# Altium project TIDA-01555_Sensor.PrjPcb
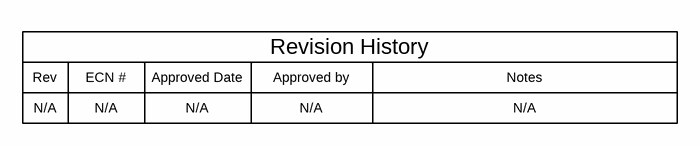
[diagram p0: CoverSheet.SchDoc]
CopyrightYear: 2017; PCB_Layout: Prasanna Rajagopal; PCB_Rev: E1; PRJ_Customer: Public Release; PRJ_Engineer: Prasanna Rajagopal; PRJ_Number: TIDA-01555; PRJ_Title: Enhanced Interface Reference Design to Connect Multiple ADCs to Processor for Input Expansion (48ch); SCH_Rev: E1; TechSupport: http://www.ti.com/support; TID: TIDA-01555
5 sheets, 139 parts. Net scope: global (net labels, ports and power ports of the same name join across sheets).
Board file: PCB.PcbDoc
Sheets:
  CoverSheet.SchDoc
  BlankSheet.SchDoc
  EVM_Hardware.SchDoc
  CT.SchDoc
  PT.SchDoc

## Sheet CoverSheet.SchDoc
size 431 x 279 mm; Date: Not shown in title block; ApprovedBy: Not shown in title block; CheckedBy: Not shown in title block; Author: Not shown in title block; CompanyName: Not shown in title block; Engineer: Not shown in title block; Organization: Not shown in title block; Address1: Not shown in title block; Address2: Not shown in title block; Address3: Not shown in title block; Address4: Not shown in title block; DocumentNumber: 1; Revision: Use project parameter SCH_Rev; SheetNumber: 1; SheetTotal: 3; PageSetup: Record=PageOptions¦CenterHorizontal=True¦CenterVertical=True¦PrintScale=1.00¦XCorrection=1.00¦YCorrection=1.00¦PrintKind=0¦BorderSize=5000000¦LeftOffset=0¦BottomOffset=0¦Orientation=2¦PaperLength=1000¦PaperWidth=1000¦Scale=100¦PaperSource=15¦PrintQuality=600¦MediaType=1¦DitherType=10¦PaperKind=Letter¦PrintScaleMode=1

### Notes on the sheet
- Rev
- N/A
- ECN #
- Approved Date
- Approved by
- Revision History
- Notes

## Sheet BlankSheet.SchDoc
size 431 x 279 mm; Date: Not shown in title block; ApprovedBy: Not shown in title block; CheckedBy: Not shown in title block; Author: Not shown in title block; CompanyName: Not shown in title block; Engineer: Not shown in title block; Organization: Not shown in title block; Address1: Not shown in title block; Address2: Not shown in title block; Address3: Not shown in title block; Address4: Not shown in title block; DocumentNumber: 1; Revision: Use project parameter SCH_Rev; SheetNumber: 2; SheetTotal: 3; PageSetup: Record=PageOptions¦CenterHorizontal=True¦CenterVertical=True¦PrintScale=1.00¦XCorrection=1.00¦YCorrection=1.00¦PrintKind=0¦BorderSize=5000000¦LeftOffset=0¦BottomOffset=0¦Orientation=2¦PaperLength=1000¦PaperWidth=1000¦Scale=100¦PaperSource=15¦PrintQuality=600¦MediaType=1¦DitherType=10¦PaperKind=Letter¦PrintScaleMode=1

## Sheet EVM_Hardware.SchDoc
size 431 x 279 mm; Date: Not shown in title block; ApprovedBy: Not shown in title block; CheckedBy: Not shown in title block; Author: Not shown in title block; CompanyName: Not shown in title block; Engineer: Not shown in title block; Organization: Not shown in title block; Address1: Not shown in title block; Address2: Not shown in title block; Address3: Not shown in title block; Address4: Not shown in title block; DocumentNumber: 1; Revision: Use project parameter SCH_Rev; SheetNumber: 3; SheetTotal: 3; PageSetup: Record=PageOptions¦CenterHorizontal=True¦CenterVertical=True¦PrintScale=1.00¦XCorrection=1.00¦YCorrection=1.00¦PrintKind=0¦BorderSize=5000000¦LeftOffset=0¦BottomOffset=0¦Orientation=2¦PaperLength=1000¦PaperWidth=1000¦Scale=100¦PaperSource=15¦PrintQuality=600¦MediaType=1¦DitherType=10¦PaperKind=Letter¦PrintScaleMode=1
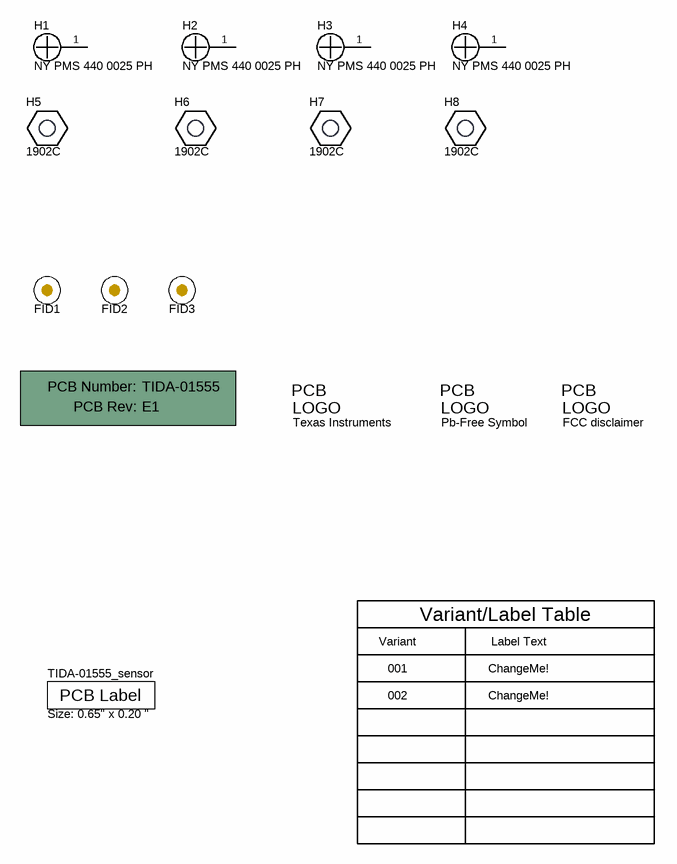
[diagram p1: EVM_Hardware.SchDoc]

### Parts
!PCB1  Printed Circuit Board  (value not drawn)  (mechanical)
FID1  Fiducial  [Fiducial10-20]  (value not drawn)
FID2  Fiducial  [Fiducial10-20]  (value not drawn)
FID3  Fiducial  [Fiducial10-20]  (value not drawn)
H1  NY PMS 440 0025 PH  [NY PMS 440 0025 PH]
H2  NY PMS 440 0025 PH  [NY PMS 440 0025 PH]
H3  NY PMS 440 0025 PH  [NY PMS 440 0025 PH]
H4  NY PMS 440 0025 PH  [NY PMS 440 0025 PH]
H5  1902C  [Keystone_1902C]
H6  1902C  [Keystone_1902C]
H7  1902C  [Keystone_1902C]
H8  1902C  [Keystone_1902C]
Logo1  Texas Instruments  [TI_Stacked_Overlay_Small]  (no BOM)
Logo2  Pb-Free Symbol  [Pb-Free_Overlay_Small]  (no BOM)
Logo3  FCC disclaimer  [FCC_disclaimer]  (no BOM)
TIDA-01555_sensor  Size: 0.65" x 0.20 "  [Label_650x200]

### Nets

Not connected (* = marked no-connect by the designer): H1 1; H2 1; H3 1; H4 1

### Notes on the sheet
- Variant
- Variant/Label Table
- Label Text
- 001
- 002
- ChangeMe!

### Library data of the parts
!PCB1 = PCB: Manufacturer: Any; PartNumber: TIDA-01555; SymbolCreator: a0412235
FID1-FID3 = Fiducial: Fiducial mark.  There is nothing to buy or mount.; SymbolCreator: codlsc
H1-H4 = NY PMS 440 0025 PH: Machine Screw, Round, #4-40 x 1/4, Nylon, Philips panhead; Manufacturer: B&F Fastener Supply; CompType: Hardware; SymbolCreator: codlsc; U/M: EA
H5-H8 = 1902C: Standoff, Hex, 0.5"L #4-40 Nylon; Manufacturer: Keystone; CompType: Hardware
Logo1 = TI_Logo: Texas Instrument Corporate Signature; SymbolCreator: codlsc
Logo2 = Pb-Free: SymbolCreator: a0412235
Logo3 = FCC_disclaimer: SymbolCreator: codlsc
TIDA-01555_sensor = THT-14-423-10: Thermal Transfer Printable Labels, 0.650" W x 0.200" H - 10,000 per roll; Manufacturer: Brady; SymbolCreator: a0412235; CompType: Label

## Sheet CT.SchDoc
size 431 x 279 mm; Date: Not shown in title block; ApprovedBy: Not shown in title block; CheckedBy: Not shown in title block; Author: Not shown in title block; CompanyName: Not shown in title block; Engineer: Not shown in title block; Organization: Not shown in title block; Address1: Not shown in title block; Address2: Not shown in title block; Address3: Not shown in title block; Address4: Not shown in title block; DocumentNumber: 1; Revision: Use project parameter SCH_Rev; SheetNumber: 2; SheetTotal: 3; PageSetup: Record=PageOptions¦CenterHorizontal=True¦CenterVertical=True¦PrintScale=1.00¦XCorrection=1.00¦YCorrection=1.00¦PrintKind=0¦BorderSize=5000000¦LeftOffset=0¦BottomOffset=0¦Orientation=2¦PaperLength=1000¦PaperWidth=1000¦Scale=100¦PaperSource=15¦PrintQuality=600¦MediaType=1¦DitherType=10¦PaperKind=Letter¦PrintScaleMode=1
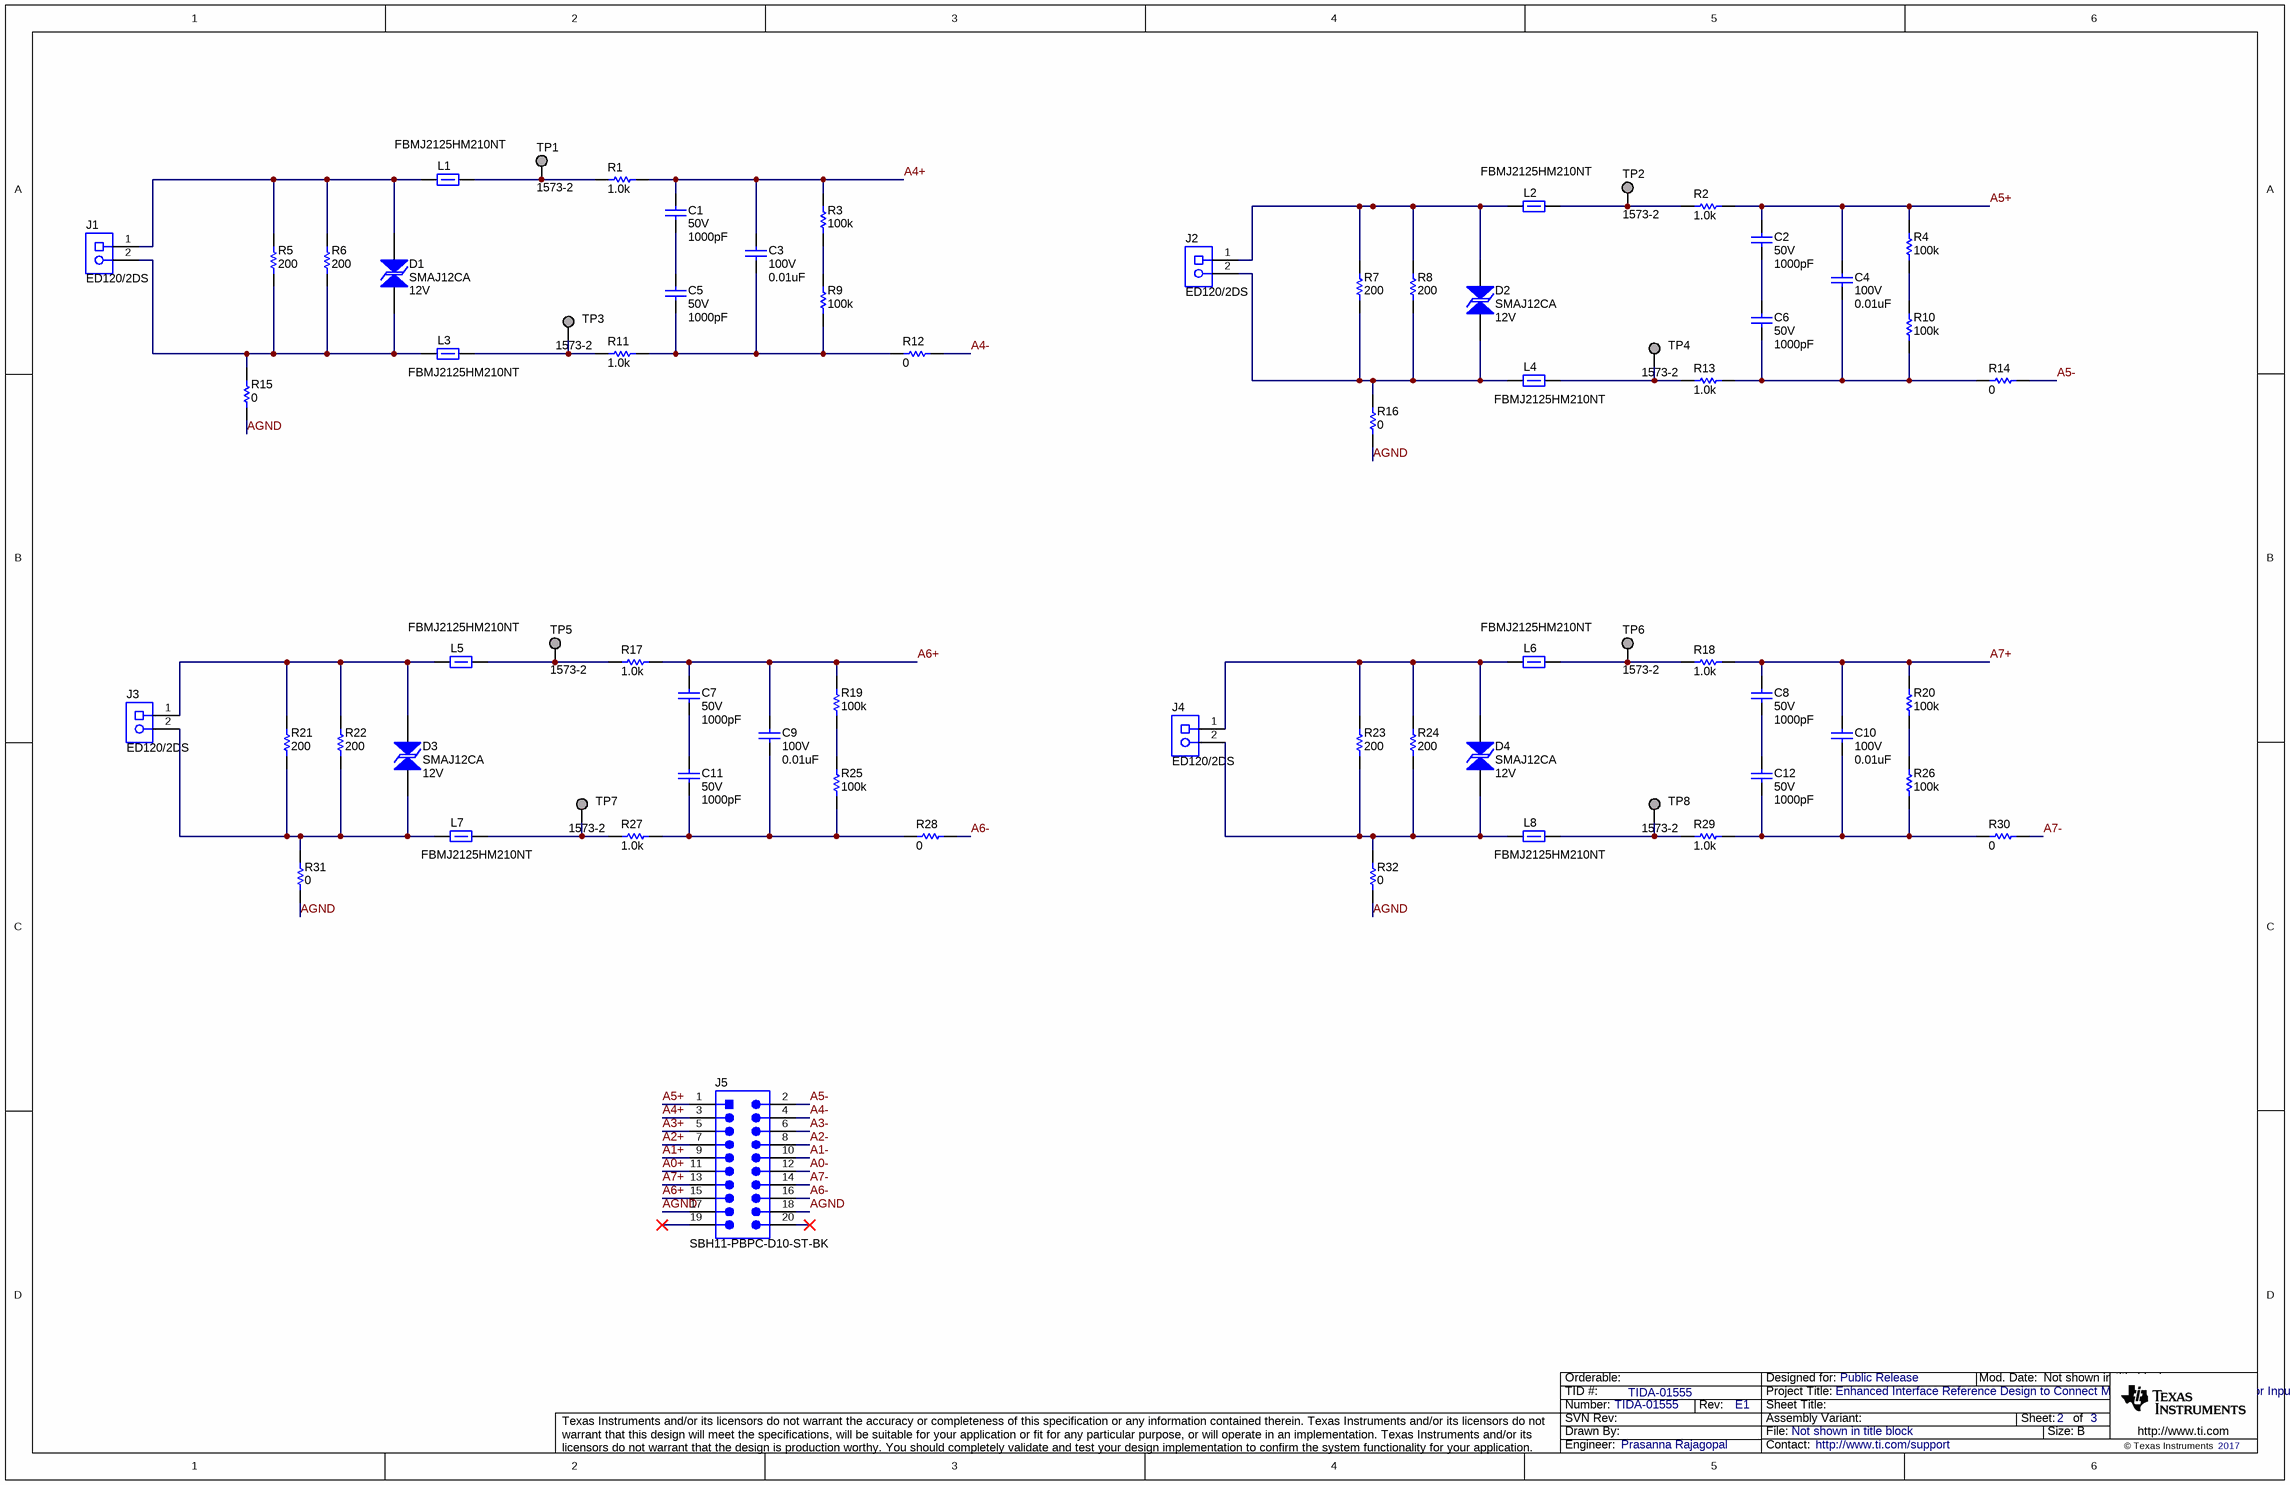
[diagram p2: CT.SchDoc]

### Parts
C1  VDC_V: 50V  ValueDisplayed: 1000pF  [0603]  (hidden comment: C0603X102K5RACTU)
C2  VDC_V: 50V  ValueDisplayed: 1000pF  [0603]  (hidden comment: C0603X102K5RACTU)
C3  VDC_V: 100V  ValueDisplayed: 0.01uF  [0603]  (hidden comment: 06031C103JAT2A)
C4  VDC_V: 100V  ValueDisplayed: 0.01uF  [0603]  (hidden comment: 06031C103JAT2A)
C5  VDC_V: 50V  ValueDisplayed: 1000pF  [0603]  (hidden comment: C0603X102K5RACTU)
C6  VDC_V: 50V  ValueDisplayed: 1000pF  [0603]  (hidden comment: C0603X102K5RACTU)
C7  VDC_V: 50V  ValueDisplayed: 1000pF  [0603]  (hidden comment: C0603X102K5RACTU)
C8  VDC_V: 50V  ValueDisplayed: 1000pF  [0603]  (hidden comment: C0603X102K5RACTU)
C9  VDC_V: 100V  ValueDisplayed: 0.01uF  [0603]  (hidden comment: 06031C103JAT2A)
C10  VDC_V: 100V  ValueDisplayed: 0.01uF  [0603]  (hidden comment: 06031C103JAT2A)
C11  VDC_V: 50V  ValueDisplayed: 1000pF  [0603]  (hidden comment: C0603X102K5RACTU)
C12  VDC_V: 50V  ValueDisplayed: 1000pF  [0603]  (hidden comment: C0603X102K5RACTU)
D1  SMAJ12CA  value 12V  [SMA]
D2  SMAJ12CA  value 12V  [SMA]
D3  SMAJ12CA  value 12V  [SMA]
D4  SMAJ12CA  value 12V  [SMA]
J1  ED120/2DS  [On-Shore_ED120_2DS]
J2  ED120/2DS  [On-Shore_ED120_2DS]
J3  ED120/2DS  [On-Shore_ED120_2DS]
J4  ED120/2DS  [On-Shore_ED120_2DS]
J5  SBH11-PBPC-D10-ST-BK  [Sullins_SBH11-xxxC-D10-ST]
L1  FBMJ2125HM210NT  [0805_HV]
L2  FBMJ2125HM210NT  [0805_HV]
L3  FBMJ2125HM210NT  [0805_HV]
L4  FBMJ2125HM210NT  [0805_HV]
L5  FBMJ2125HM210NT  [0805_HV]
L6  FBMJ2125HM210NT  [0805_HV]
L7  FBMJ2125HM210NT  [0805_HV]
L8  FBMJ2125HM210NT  [0805_HV]
R1  ValueDisplayed: 1.0k  [0603]  (hidden comment: CRCW06031K00JNEA)
R2  ValueDisplayed: 1.0k  [0603]  (hidden comment: CRCW06031K00JNEA)
R3  ValueDisplayed: 100k  [0603]  (hidden comment: RC0603FR-07100KL)
R4  ValueDisplayed: 100k  [0603]  (hidden comment: RC0603FR-07100KL)
R5  ValueDisplayed: 200  [0603]  (hidden comment: CRCW0603200RFKEA)
R6  ValueDisplayed: 200  [0603]  (hidden comment: CRCW0603200RFKEA)
R7  ValueDisplayed: 200  [0603]  (hidden comment: CRCW0603200RFKEA)
R8  ValueDisplayed: 200  [0603]  (hidden comment: CRCW0603200RFKEA)
R9  ValueDisplayed: 100k  [0603]  (hidden comment: RC0603FR-07100KL)
R10  ValueDisplayed: 100k  [0603]  (hidden comment: RC0603FR-07100KL)
R11  ValueDisplayed: 1.0k  [0603]  (hidden comment: CRCW06031K00JNEA)
R12  ValueDisplayed: 0  [0603]  (hidden comment: CRCW06030000Z0EA)
R13  ValueDisplayed: 1.0k  [0603]  (hidden comment: CRCW06031K00JNEA)
R14  ValueDisplayed: 0  [0603]  (hidden comment: CRCW06030000Z0EA)
R15  ValueDisplayed: 0  [0603]  (hidden comment: CRCW06030000Z0EA)
R16  ValueDisplayed: 0  [0603]  (hidden comment: CRCW06030000Z0EA)
R17  ValueDisplayed: 1.0k  [0603]  (hidden comment: CRCW06031K00JNEA)
R18  ValueDisplayed: 1.0k  [0603]  (hidden comment: CRCW06031K00JNEA)
R19  ValueDisplayed: 100k  [0603]  (hidden comment: RC0603FR-07100KL)
R20  ValueDisplayed: 100k  [0603]  (hidden comment: RC0603FR-07100KL)
R21  ValueDisplayed: 200  [0603]  (hidden comment: CRCW0603200RFKEA)
R22  ValueDisplayed: 200  [0603]  (hidden comment: CRCW0603200RFKEA)
R23  ValueDisplayed: 200  [0603]  (hidden comment: CRCW0603200RFKEA)
R24  ValueDisplayed: 200  [0603]  (hidden comment: CRCW0603200RFKEA)
R25  ValueDisplayed: 100k  [0603]  (hidden comment: RC0603FR-07100KL)
R26  ValueDisplayed: 100k  [0603]  (hidden comment: RC0603FR-07100KL)
R27  ValueDisplayed: 1.0k  [0603]  (hidden comment: CRCW06031K00JNEA)
R28  ValueDisplayed: 0  [0603]  (hidden comment: CRCW06030000Z0EA)
R29  ValueDisplayed: 1.0k  [0603]  (hidden comment: CRCW06031K00JNEA)
R30  ValueDisplayed: 0  [0603]  (hidden comment: CRCW06030000Z0EA)
R31  ValueDisplayed: 0  [0603]  (hidden comment: CRCW06030000Z0EA)
R32  ValueDisplayed: 0  [0603]  (hidden comment: CRCW06030000Z0EA)
TP1  1573-2  [Keystone1573-2]
TP2  1573-2  [Keystone1573-2]
TP3  1573-2  [Keystone1573-2]
TP4  1573-2  [Keystone1573-2]
TP5  1573-2  [Keystone1573-2]
TP6  1573-2  [Keystone1573-2]
TP7  1573-2  [Keystone1573-2]
TP8  1573-2  [Keystone1573-2]

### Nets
A0+: J5.11
A0-: J5.12
A1+: J5.9
A1-: J5.10
A2+: J5.7
A2-: J5.8
A3+: J5.5
A3-: J5.6
A4+: C1.1 C3.1 J5.3 R1.1 R3.2
A4-: J5.4 R12.2
A5+: C2.1 C4.1 J5.1 R2.1 R4.2
A5-: J5.2 R14.2
A6+: C7.1 C9.1 J5.15 R17.1 R19.2
A6-: J5.16 R28.2
A7+: C8.1 C10.1 J5.13 R18.1 R20.2
A7-: J5.14 R30.2
AGND: J5.17 J5.18 R15.1 R16.1 R31.1 R32.1
NetC1_2: C1.2 C5.1
NetC2_2: C2.2 C6.1
NetC3_2: C3.2 C5.2 R9.1 R11.1 R12.1
NetC4_2: C4.2 C6.2 R10.1 R13.1 R14.1
NetC7_2: C7.2 C11.1
NetC8_2: C8.2 C12.1
NetC9_2: C9.2 C11.2 R25.1 R27.1 R28.1
NetC10_2: C10.2 C12.2 R26.1 R29.1 R30.1
NetD1_1: D1.1 J1.2 L3.1 R5.1 R6.1 R15.2
NetD1_2: D1.2 J1.1 L1.1 R5.2 R6.2
NetD2_1: D2.1 J2.2 L4.1 R7.1 R8.1 R16.2
NetD2_2: D2.2 J2.1 L2.1 R7.2 R8.2
NetD3_1: D3.1 J3.2 L7.1 R21.1 R22.1 R31.2
NetD3_2: D3.2 J3.1 L5.1 R21.2 R22.2
NetD4_1: D4.1 J4.2 L8.1 R23.1 R24.1 R32.2
NetD4_2: D4.2 J4.1 L6.1 R23.2 R24.2
NetL1_2: L1.2 R1.2 TP1.1
NetL2_2: L2.2 R2.2 TP2.1
NetL3_2: L3.2 R11.2 TP3.1
NetL4_2: L4.2 R13.2 TP4.1
NetL5_2: L5.2 R17.2 TP5.1
NetL6_2: L6.2 R18.2 TP6.1
NetL7_2: L7.2 R27.2 TP7.1
NetL8_2: L8.2 R29.2 TP8.1
NetR3_1: R3.1 R9.2
NetR4_1: R4.1 R10.2
NetR19_1: R19.1 R25.2
NetR20_1: R20.1 R26.2

Not connected (* = marked no-connect by the designer): J5 19* 20*

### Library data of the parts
C1 C2 C5-C8 C11 C12 = CMP-0006976-5: CAP, CERM, 1000 pF, 50 V, +/- 10%, X7R, 0603; Manufacturer: Kemet; TaMin_C: -55°C; Polarized: N; SizeAreaWB_mm2: 4.68; Value1: Unknown; U/M: EA; Value: 1000pF; TaMax_C: 125°C; SizeZ_mm: 1; SizeX_mm: 1.6; SizeY_mm: 0.8; SizeArea_mm2: 1.28; Cap_F: 1nF; AEC Category: Q200
C3 C4 C9 C10 = CMP-0006726-4: CAP, CERM, 0.01 uF, 100 V, +/- 5%, X7R, 0603; Manufacturer: AVX; TaMin_C: -55°C; ESR_ohm: 0.098; Polarized: N; SizeAreaWB_mm2: 4.68; Value1: 0.098 ohm; U/M: EA; Value: 0.01uF; TaMax_C: 125°C; SizeZ_mm: 1; SizeX_mm: 1.6; SizeY_mm: 0.8; SizeArea_mm2: 1.28; Cap_F: 10nF; AEC Category: Q200
D1-D4 = CMP-0005430-2: Diode, TVS, Bi, 12 V, SMA; Manufacturer: Littelfuse; Power_W: 3.3W; SizeAreaWB_mm2: 37.3428; RJA_CperW: 120; U/M: EA; SizeZ_mm: 2.87; SizeX_mm: 5.59; SizeY_mm: 2.92; SizeArea_mm2: 16.3228; AEC Category: Q101
J1-J4 = CMP-0074910-1: Terminal Block, 5.08 mm, 2x1, Brass, TH; Manufacturer: On-Shore Technology; Cert_VDE: Y; CNHeader: False; Current_A: 15A; Green_Lifecycle: Not Set; Shrouded: N; Gender: Female; Green_REACh: Incomplete; Voltage_V: 300V; Row_Count: 1; Pitch_mm: 5.08; CT: True
J5 = SBH11-PBPC-D10-ST-BK: Header (Shrouded), 2.54mm, 10x2, Gold, Black, TH; Manufacturer: Sullins Connector Solutions; SymbolCreator: a0412235; Pitch_mm: 2.54; Gender: Male; Shrouded: Y; Row_Count: 2; Current_A: 3; Voltage_V: 1000; Green_Lifecycle: Not Set; Green_REACh: Incomplete
L1-L8 = CMP-0003375-1: Ferrite Bead, 21 ohm @ 100 MHz, 6 A, 0805; Manufacturer: Taiyo Yuden; ZTyp@100MHz_Ohm: 21; SizeAreaWB_mm2: 6.75; DCR_ohm: 4m; Value1: 0.004 ohm; Value: 21 ohm; Imax_A: 6A; SizeZ_mm: 1.45; SizeX_mm: 2; SizeY_mm: 1.25; SizeArea_mm2: 2.5
R1 R2 R11 R13 R17 R18 R27 R29 = CRCW06031K00JNEA: RES, 1.0 k, 5%, 0.1 W, 0603; Manufacturer: Vishay-Dale; CompType: Resistor; Value: 1.0k; Res_ohm: 1000; Value_Code: 1k00; Tolerance_%: 5; Power_W: 0.1; Value2: 0.1W; VDC_V: 75; TempCo: 200 ppm/C; SizeArea_mm2: 1.28; SizeX_mm: 1.6; SizeY_mm: 0.8; SizeZ_mm: 1; EIA_Code: E24; U/M: EA; AEC Category: Q200; Green_Lifecycle: Active; Green_REACh: Passed
R3 R4 R9 R10 R19 R20 R25 R26 = CMP-0022735-3: RES, 100 k, 1%, 0.1 W, 0603; Manufacturer: Yageo America; Power_W: 100mW; TempCo: 200 ppm/C; U/M: EA; Value: 100k; EIA_Code: E96; SizeX_mm: 1.6; SizeY_mm: 0.8; SizeZ_mm: 1; Value2: 0.1W; SizeArea_mm2: 1.28; VDC_V: 150V; AEC Category: Q200
R5-R8 R21-R24 = CRCW0603200RFKEA: RES, 200, 1%, 0.1 W, 0603; Manufacturer: Vishay-Dale; CompType: Resistor; Value: 200; Value_Code: 200R; Tolerance_%: 1; Power_W: 0.1; Value2: 0.1W; VDC_V: 75; TempCo: 100 ppm/C; SizeArea_mm2: 1.28; SizeX_mm: 1.6; SizeY_mm: 0.8; EIA_Code: E96; U/M: EA; AEC Category: Q200; Green_Lifecycle: Active; Green_REACh: Passed
R12 R14 R28 R30 = CMP-0025697-3: RES, 0, 5%, 0.1 W, 0603; Manufacturer: Vishay-Dale; Power_W: 100mW; TempCo: 200 ppm/C; Value_Code: 0000; U/M: EA; Value: 0; EIA_Code: E24; SizeX_mm: 1.6; SizeY_mm: 0.8; SizeZ_mm: 1; Value2: 0.1W; SizeArea_mm2: 1.28; VDC_V: 75V; AEC Category: Q200
R15 R16 R31 R32 = CMP-0025697-3: RES, 0, 5%, 0.1 W, 0603; Manufacturer: Vishay-Dale; Power_W: 100mW; TempCo: 200 ppm/C; Value_Code: 0000; U/M: EA; Value: 0; EIA_Code: E24; SizeX_mm: 1.6; SizeY_mm: 0.8; SizeZ_mm: 1; Value2: 0.1W; SizeArea_mm2: 1.28; CompType: Resistor; VDC_V: 75V; AEC Category: Q200
TP1-TP8 = CMP-0055119-1: Terminal, Turret, TH, Double; Manufacturer: Keystone; CT: FALSE; Green_REACh: Passed; CompType: Turret Terminal; Green_Lifecycle: Active

## Sheet PT.SchDoc
size 431 x 279 mm; Date: Not shown in title block; ApprovedBy: Not shown in title block; CheckedBy: Not shown in title block; Author: Not shown in title block; CompanyName: Not shown in title block; Engineer: Not shown in title block; Organization: Not shown in title block; Address1: Not shown in title block; Address2: Not shown in title block; Address3: Not shown in title block; Address4: Not shown in title block; DocumentNumber: 1; Revision: Use project parameter SCH_Rev; SheetNumber: 2; SheetTotal: 3; PageSetup: Record=PageOptions¦CenterHorizontal=True¦CenterVertical=True¦PrintScale=1.00¦XCorrection=1.00¦YCorrection=1.00¦PrintKind=0¦BorderSize=5000000¦LeftOffset=0¦BottomOffset=0¦Orientation=2¦PaperLength=1000¦PaperWidth=1000¦Scale=100¦PaperSource=15¦PrintQuality=600¦MediaType=1¦DitherType=10¦PaperKind=Letter¦PrintScaleMode=1
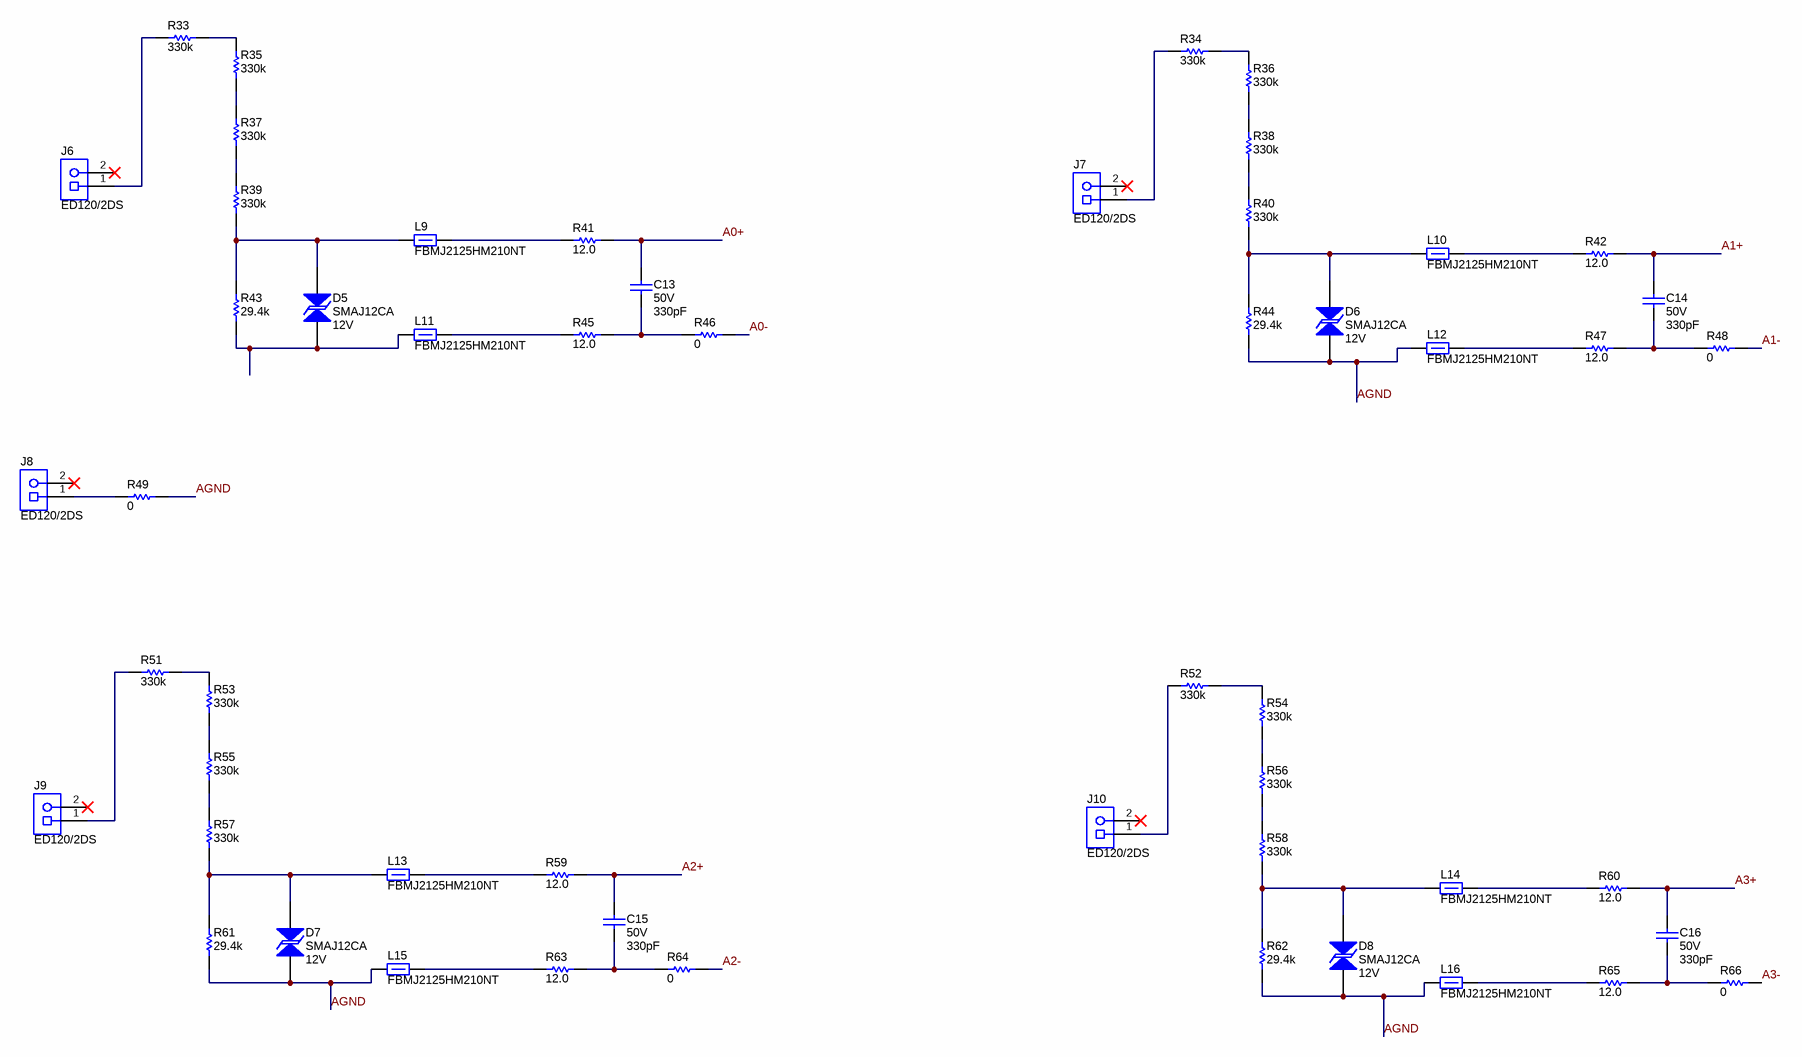
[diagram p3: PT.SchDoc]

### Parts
C13  VDC_V: 50V  ValueDisplayed: 330pF  [0805_HV]  (hidden comment: 08055A331KAT2A)
C14  VDC_V: 50V  ValueDisplayed: 330pF  [0805_HV]  (hidden comment: 08055A331KAT2A)
C15  VDC_V: 50V  ValueDisplayed: 330pF  [0805_HV]  (hidden comment: 08055A331KAT2A)
C16  VDC_V: 50V  ValueDisplayed: 330pF  [0805_HV]  (hidden comment: 08055A331KAT2A)
D5  SMAJ12CA  value 12V  [SMA]
D6  SMAJ12CA  value 12V  [SMA]
D7  SMAJ12CA  value 12V  [SMA]
D8  SMAJ12CA  value 12V  [SMA]
J6  ED120/2DS  [On-Shore_ED120_2DS]
J7  ED120/2DS  [On-Shore_ED120_2DS]
J8  ED120/2DS  [On-Shore_ED120_2DS]
J9  ED120/2DS  [On-Shore_ED120_2DS]
J10  ED120/2DS  [On-Shore_ED120_2DS]
L9  FBMJ2125HM210NT  [0805_HV]
L10  FBMJ2125HM210NT  [0805_HV]
L11  FBMJ2125HM210NT  [0805_HV]
L12  FBMJ2125HM210NT  [0805_HV]
L13  FBMJ2125HM210NT  [0805_HV]
L14  FBMJ2125HM210NT  [0805_HV]
L15  FBMJ2125HM210NT  [0805_HV]
L16  FBMJ2125HM210NT  [0805_HV]
R33  ValueDisplayed: 330k  [1206]  (hidden comment: RC1206FR-07330KL)
R34  ValueDisplayed: 330k  [1206]  (hidden comment: RC1206FR-07330KL)
R35  ValueDisplayed: 330k  [1206]  (hidden comment: RC1206FR-07330KL)
R36  ValueDisplayed: 330k  [1206]  (hidden comment: RC1206FR-07330KL)
R37  ValueDisplayed: 330k  [1206]  (hidden comment: RC1206FR-07330KL)
R38  ValueDisplayed: 330k  [1206]  (hidden comment: RC1206FR-07330KL)
R39  ValueDisplayed: 330k  [1206]  (hidden comment: RC1206FR-07330KL)
R40  ValueDisplayed: 330k  [1206]  (hidden comment: RC1206FR-07330KL)
R41  ValueDisplayed: 12.0  [0603]  (hidden comment: RC0603FR-0712RL)
R42  ValueDisplayed: 12.0  [0603]  (hidden comment: RC0603FR-0712RL)
R43  ValueDisplayed: 29.4k  [1206]  (hidden comment: CRCW120629K4FKEA)
R44  ValueDisplayed: 29.4k  [1206]  (hidden comment: CRCW120629K4FKEA)
R45  ValueDisplayed: 12.0  [0603]  (hidden comment: RC0603FR-0712RL)
R46  ValueDisplayed: 0  [0603]  (hidden comment: CRCW06030000Z0EA)
R47  ValueDisplayed: 12.0  [0603]  (hidden comment: RC0603FR-0712RL)
R48  ValueDisplayed: 0  [0603]  (hidden comment: CRCW06030000Z0EA)
R49  ValueDisplayed: 0  [0603]  (hidden comment: CRCW06030000Z0EA)
R51  ValueDisplayed: 330k  [1206]  (hidden comment: RC1206FR-07330KL)
R52  ValueDisplayed: 330k  [1206]  (hidden comment: RC1206FR-07330KL)
R53  ValueDisplayed: 330k  [1206]  (hidden comment: RC1206FR-07330KL)
R54  ValueDisplayed: 330k  [1206]  (hidden comment: RC1206FR-07330KL)
R55  ValueDisplayed: 330k  [1206]  (hidden comment: RC1206FR-07330KL)
R56  ValueDisplayed: 330k  [1206]  (hidden comment: RC1206FR-07330KL)
R57  ValueDisplayed: 330k  [1206]  (hidden comment: RC1206FR-07330KL)
R58  ValueDisplayed: 330k  [1206]  (hidden comment: RC1206FR-07330KL)
R59  ValueDisplayed: 12.0  [0603]  (hidden comment: RC0603FR-0712RL)
R60  ValueDisplayed: 12.0  [0603]  (hidden comment: RC0603FR-0712RL)
R61  ValueDisplayed: 29.4k  [1206]  (hidden comment: CRCW120629K4FKEA)
R62  ValueDisplayed: 29.4k  [1206]  (hidden comment: CRCW120629K4FKEA)
R63  ValueDisplayed: 12.0  [0603]  (hidden comment: RC0603FR-0712RL)
R64  ValueDisplayed: 0  [0603]  (hidden comment: CRCW06030000Z0EA)
R65  ValueDisplayed: 12.0  [0603]  (hidden comment: RC0603FR-0712RL)
R66  ValueDisplayed: 0  [0603]  (hidden comment: CRCW06030000Z0EA)

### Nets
A0+: C13.1 R41.2
A0-: R46.2
A1+: C14.1 R42.2
A1-: R48.2
A2+: C15.1 R59.2
A2-: R64.2
A3+: C16.1 R60.2
A3-: R66.2
AGND: D6.1 D7.1 D8.1 L12.1 L15.1 L16.1 R44.2 R49.1 R61.2 R62.2
NetC13_2: C13.2 R45.2 R46.1
NetC14_2: C14.2 R47.2 R48.1
NetC15_2: C15.2 R63.2 R64.1
NetC16_2: C16.2 R65.2 R66.1
NetD5_1: D5.1 L11.1 R43.2
NetD5_2: D5.2 L9.1 R39.1 R43.1
NetD6_2: D6.2 L10.1 R40.1 R44.1
NetD7_2: D7.2 L13.1 R57.1 R61.1
NetD8_2: D8.2 L14.1 R58.1 R62.1
NetJ6_1: J6.1 R33.2
NetJ7_1: J7.1 R34.2
NetJ8_1: J8.1 R49.2
NetJ9_1: J9.1 R51.2
NetJ10_1: J10.1 R52.2
NetL9_2: L9.2 R41.1
NetL10_2: L10.2 R42.1
NetL11_2: L11.2 R45.1
NetL12_2: L12.2 R47.1
NetL13_2: L13.2 R59.1
NetL14_2: L14.2 R60.1
NetL15_2: L15.2 R63.1
NetL16_2: L16.2 R65.1
NetR33_1: R33.1 R35.2
NetR34_1: R34.1 R36.2
NetR35_1: R35.1 R37.2
NetR36_1: R36.1 R38.2
NetR37_1: R37.1 R39.2
NetR38_1: R38.1 R40.2
NetR51_1: R51.1 R53.2
NetR52_1: R52.1 R54.2
NetR53_1: R53.1 R55.2
NetR54_1: R54.1 R56.2
NetR55_1: R55.1 R57.2
NetR56_1: R56.1 R58.2

Not connected (* = marked no-connect by the designer): J6 2*; J7 2*; J8 2*; J9 2*; J10 2*

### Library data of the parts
C13-C16 = CMP-0007609-2: CAP, CERM, 330 pF, 50 V, +/- 10%, C0G/NP0, 0805; Manufacturer: AVX; TaMin_C: -55°C; ESR_ohm: 1.89d; Polarized: N; SizeAreaWB_mm2: 6.75; Value1: 0.189 ohm; U/M: EA; Value: 330pF; TaMax_C: 125°C; SizeZ_mm: 1.45; SizeX_mm: 2; SizeY_mm: 1.25; Cap_Case: 0805; SizeArea_mm2: 2.5; AEC Category: Q200
D5-D8 = CMP-0005430-2: as D1 on sheet CT
J6-J10 = CMP-0074910-1: as J1 on sheet CT
L9-L16 = CMP-0003375-1: as L1 on sheet CT
R33-R40 R51-R58 = CMP-0018205-2: RES, 330 k, 1%, 0.25 W, 1206; Manufacturer: Yageo America; Power_W: 250mW; TempCo: 100 ppm/C; U/M: EA; Value: 330k; SizeX_mm: 3.2; SizeY_mm: 1.6; SizeZ_mm: 1.35; Value2: 0.25W; SizeArea_mm2: 5.12; VDC_V: 200V; AEC Category: Q200
R41 R42 R45 R47 R59 R60 R63 R65 = CMP-0022783-2: RES, 12.0, 1%, 0.1 W, 0603; Manufacturer: Yageo America; Power_W: 100mW; TempCo: 200 ppm/C; Value_Code: 12R0; U/M: EA; Value: 12.0; Res_ohm: 12; SizeX_mm: 1.6; SizeY_mm: 0.8; SizeZ_mm: 1; Value2: 0.1W; SizeArea_mm2: 1.28; VDC_V: 150V; AEC Category: Q200
R43 R44 R61 R62 = CMP-0016842-2: RES, 29.4 k, 1%, 0.25 W, 1206; Manufacturer: Vishay-Dale; Power_W: 250mW; TempCo: 100 ppm/C; Value_Code: 29k4; U/M: EA; Value: 29.4k; SizeX_mm: 3.2; SizeY_mm: 1.6; SizeZ_mm: 1.35; Value2: 0.25W; SizeArea_mm2: 5.12; VDC_V: 200V; AEC Category: Q200; EIA_Code: E96
R46 R48 R64 R66 = CMP-0025697-3: as R12 on sheet CT
R49 = CMP-0025697-3: as R15 on sheet CT

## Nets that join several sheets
A0+: CT (J5.11), PT (C13.1 R41.2)
A0-: CT (J5.12), PT (R46.2)
A1+: CT (J5.9), PT (C14.1 R42.2)
A1-: CT (J5.10), PT (R48.2)
A2+: CT (J5.7), PT (C15.1 R59.2)
A2-: CT (J5.8), PT (R64.2)
A3+: CT (J5.5), PT (C16.1 R60.2)
A3-: CT (J5.6), PT (R66.2)
AGND: CT (6 pins), PT (10 pins)

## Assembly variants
001: not fitted FID1 FID2 FID3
